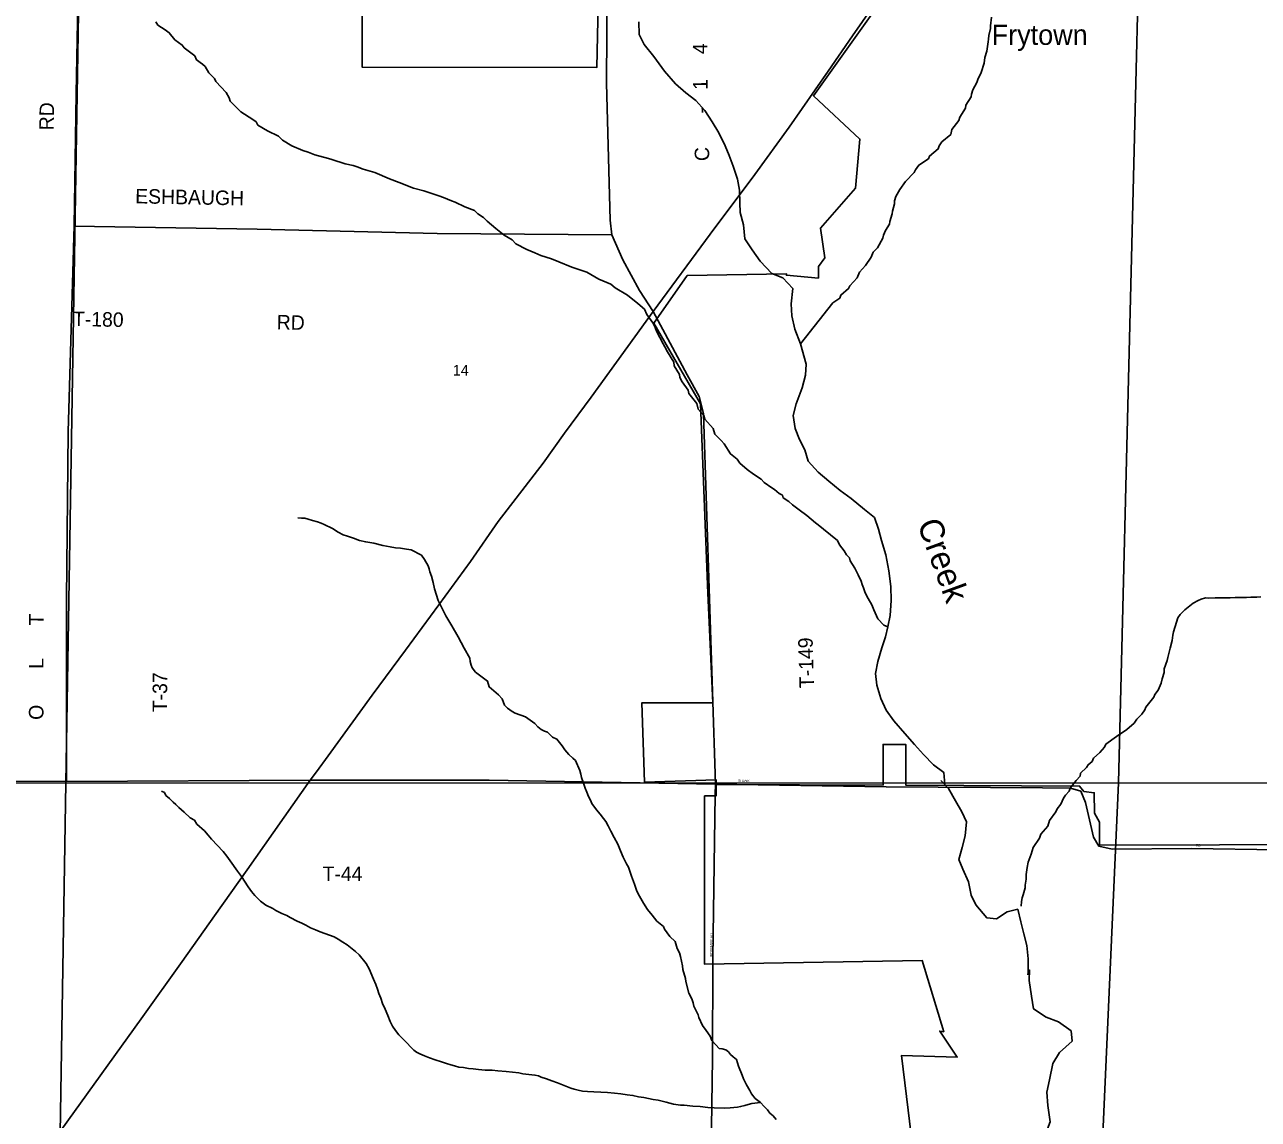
# Model space of a CAD drawing. Extents: x 1312308 to 1684953, y 460642 to 865172.
# Drawn here: x 1464469 to 1470845, y 623330 to 628989 of the extents above; entities that cross this region are included whole.
import ezdxf

# ---------------------------------------------------------------- set-up
doc = ezdxf.new("R2010")
doc.units = 0
for name, color, linetype in [('GM_X_City_Street', 7, 'Continuous'), ('GM_X_City_Street_Text', 7, 'Continuous'), ('GM_X_Corporation', 7, 'Continuous'), ('GM_X_County_Road', 7, 'Continuous'), ('GM_X_County_Road_Text', 7, 'Continuous'), ('GM_X_Minor_River', 7, 'Continuous'), ('GM_X_Minor_River_Text', 7, 'Continuous'), ('GM_X_Section', 7, 'Continuous'), ('GM_X_Section_Text', 7, 'Continuous'), ('GM_X_State_Route', 7, 'Continuous'), ('GM_X_Township_Road', 7, 'Continuous'), ('GM_X_Township_Road_Text', 7, 'Continuous'), ('GM_X_Unincorporated_Text', 7, 'Continuous')]:
    doc.layers.add(name, color=color, linetype=linetype)

msp = doc.modelspace()

# ---------------------------------------------------------------- linework, layer by layer
at = {"layer": 'GM_X_City_Street'}
for points in [[(1468038.3, 625009.5), (1468039.1, 625062.4), (1468023.7, 625542.1)], [(1468026.3, 624163), (1468038.3, 625009.5)], [(1468039.1, 625062.4), (1468920.9, 625048.3), (1469729.1, 625044.2), (1469873.4, 625042.2), (1469927.1, 625026.7), (1469951.5, 624967.8), (1469992.5, 624788.1), (1470019.9, 624742.8), (1470089, 624727.2), (1470498.2, 624730), (1470950.3, 624722.5), (1471309.2, 624721.6)]]:
    msp.add_lwpolyline(points, dxfattribs=at)
at = {"layer": 'GM_X_Corporation'}
for points in [[(1467456.4, 630241.5), (1467426.6, 628767.9), (1466212.4, 628769.8), (1466212.4, 629213.7)], [(1471264.1, 624750.7), (1470023.6, 624747.6), (1470024, 624865.5), (1469998.5, 624912.4), (1469996.5, 625018.4), (1469943.5, 625025.5), (1469920.5, 625053.1), (1469022.4, 625058.3), (1469022.4, 625268.4), (1468905.4, 625268.3), (1468905.4, 625058.3), (1468042.8, 625060.8), (1468042, 625085.8), (1467672.7, 625072.9), (1467658.4, 625482.7), (1468025.4, 625482.8), (1467999.5, 626049.3), (1467962.4, 627028.9), (1467721.4, 627446.5), (1467893.5, 627692.2), (1468405.9, 627701.2), (1468405.9, 627693.2), (1468571.2, 627678.8), (1468571.2, 627738.8), (1468604.3, 627782.7), (1468582.8, 627936.2), (1468763.2, 628143.7), (1468785.4, 628397.7), (1468545.3, 628621.6), (1468958.7, 629201.3)], [(1469152.5, 622416.7), (1469001.4, 623660.4), (1469288.4, 623652.1), (1469198, 623786), (1469219.3, 623782.7), (1469106.6, 624151.5), (1467983.1, 624131.8), (1467983.1, 625002), (1468042.6, 625002.4), (1468042.8, 625060.8), (1468905.4, 625058.3), (1468905.4, 625268.3), (1469022.4, 625268.4), (1469022.4, 625058.3), (1469920.5, 625053.1), (1469943.5, 625025.5), (1469996.5, 625018.4), (1469998.5, 624912.4), (1470024, 624865.5), (1470023.6, 624747.6), (1471264.1, 624750.7)]]:
    msp.add_lwpolyline(points, dxfattribs=at)
at = {"layer": 'GM_X_County_Road'}
for points in [[(1467717.9, 627505.5), (1467645.7, 627614.5), (1467560.2, 627773), (1467503.6, 627902.5), (1467495.6, 627978), (1467475.9, 628686), (1467479.7, 629209.1), (1467509.4, 630147.5), (1467518.7, 630244.5), (1467561.4, 630362.2), (1467592.2, 630460.3), (1467604.8, 630537.3), (1467608.5, 630663.9), (1467609.8, 630907.3), (1467613.5, 631151.9), (1467614.1, 631178.6)], [(1454210.5, 625100.4), (1455352.9, 625087.9), (1456190.5, 625056.2), (1456967.8, 625063.2), (1457105.9, 625064), (1457396.6, 625065.8), (1458239.8, 625063.3), (1459213.3, 625064), (1459508.2, 625062.6), (1459800.2, 625061.2), (1461104, 625081.4), (1462543.4, 625079.9), (1464684.9, 625077), (1465945, 625083.6)]]:
    msp.add_lwpolyline(points, dxfattribs=at)
at = {"layer": 'GM_X_Minor_River'}
for points in [[(1468479.3, 627338.4), (1468646.5, 627551.6), (1468681.4, 627574.9), (1468687.8, 627590.8), (1468726.9, 627624.1), (1468733.3, 627638), (1468770.6, 627679.3), (1468783.4, 627709.1), (1468814.5, 627744.6), (1468843.8, 627786.1), (1468854.5, 627812), (1468877.3, 627835.5), (1468904.7, 627885.1), (1468907.1, 627901.2), (1468917.8, 627925), (1468938.8, 627956.7), (1468941.1, 627970.7), (1468952.2, 628010.7), (1468954.6, 628024.7), (1468963.6, 628062.7), (1468964.1, 628078.7), (1468970.7, 628100.7), (1468991.7, 628136.4), (1469021, 628177.9), (1469066.5, 628225), (1469072.9, 628238.9), (1469089.6, 628262.7), (1469140.7, 628295.6), (1469145.1, 628309.6), (1469190.4, 628346.7), (1469194.8, 628362.7), (1469209.4, 628382.4), (1469254.7, 628421.5), (1469261.4, 628447.5), (1469296.8, 628492.9), (1469301.3, 628510.8), (1469330.6, 628556.4), (1469333.1, 628572.4), (1469360.4, 628616), (1469362.7, 628630), (1469369.3, 628651.9), (1469390.4, 628689.6), (1469394.9, 628705.6), (1469411.9, 628741.4), (1469427.2, 628789.2), (1469432, 628819.3), (1469440.9, 628851.2), (1469448.2, 628899.3), (1469450.6, 628913.3), (1469451.1, 628933.4), (1469460.1, 628969.4), (1469460.4, 628983.4), (1469465.6, 629027.5)], [(1465849.6, 628363.1), (1465802.1, 628392.4), (1465780.5, 628413), (1465724.8, 628440.5), (1465673.2, 628469.9), (1465665.6, 628486.1), (1465647.8, 628498.6), (1465586.4, 628538.3), (1465531.5, 628593.9), (1465525.9, 628610.1), (1465510.5, 628638.7), (1465457.6, 628694.2), (1465450, 628710.5), (1465420.5, 628739.3), (1465401.3, 628772), (1465387.5, 628784.4), (1465357.9, 628807.2), (1465348.4, 628827.5), (1465293.1, 628869.1), (1465283.4, 628883.4), (1465245.8, 628910.4), (1465216.6, 628947.3), (1465194.8, 628961.9), (1465157.2, 628986.9), (1465147.6, 629003.3)], [(1469224, 625060.2), (1469218.7, 625123.5), (1469165.5, 625163.2), (1469114.8, 625216.8), (1469067.9, 625268.3), (1469017.2, 625323.9), (1468960.7, 625389.8), (1468922, 625445), (1468893.5, 625506.1), (1468873.3, 625574.9), (1468866.9, 625635.3), (1468878.7, 625697.2), (1468898.6, 625766.9), (1468918.3, 625824.6), (1468929.8, 625876.5), (1468941.4, 625934.4), (1468947.5, 626012.5), (1468945.5, 626084.8), (1468935.6, 626165.4), (1468919.8, 626248.2), (1468897.7, 626323), (1468881.2, 626381.7), (1468860.7, 626440.5), (1468809.6, 626482.1), (1468740.9, 626540.2), (1468683.7, 626580), (1468624.7, 626629.8), (1468569.7, 626675.5), (1468519, 626733.1), (1468500.5, 626791.8), (1468473.8, 626844.8), (1468451.3, 626901.6), (1468441, 626968.1), (1468456.7, 627027.9), (1468487.1, 627111.4), (1468505, 627177.1), (1468508.5, 627233.2), (1468479.3, 627338.4), (1468449.2, 627415.5), (1468433, 627484.2), (1468430.7, 627546.5), (1468438.8, 627624.6), (1468388.1, 627680.2), (1468330.4, 627701.9), (1468269.8, 627765.8), (1468229.3, 627825.1), (1468190.6, 627882.4), (1468184.6, 627954.8), (1468166.2, 628017.6), (1468165.5, 628067.8), (1468163.3, 628134.1), (1468152.8, 628190.6), (1468130.5, 628257.4), (1468109.9, 628312.2), (1468089.2, 628362.9), (1468056.8, 628430.1), (1468022.2, 628487.2), (1467983.6, 628544.5), (1467936.8, 628596), (1467885.6, 628635.6), (1467832.6, 628683.2), (1467776.1, 628749), (1467719.9, 628824.9), (1467671.4, 628886.4), (1467644.6, 628937.4), (1467642.4, 629003.7)], [(1468929.8, 625876.5), (1468909.4, 625884.4), (1468878.1, 625917.4), (1468857.1, 625964.1), (1468847.8, 625990.5), (1468828.5, 626023.1), (1468813.1, 626051.7), (1468803.7, 626078), (1468798.1, 626094.2), (1468792.5, 626112.5), (1468777.3, 626145), (1468760.1, 626179.6), (1468734.8, 626216.4), (1468731.2, 626232.6), (1468715.5, 626249), (1468704, 626269.4), (1468680.6, 626300.2), (1468669.1, 626322.6), (1468598.2, 626380.6), (1468570.6, 626403.4), (1468556.8, 626413.8), (1468511.4, 626451), (1468471.9, 626480.1), (1468436.4, 626507.2), (1468418.7, 626523.7), (1468389, 626542.5), (1468385.3, 626556.6), (1468367.5, 626565.1), (1468343.8, 626585.8), (1468330, 626594.2), (1468290.4, 626621.3), (1468274.8, 626639.7), (1468235.2, 626664.8), (1468203.6, 626689.7), (1468164.2, 626722.8), (1468150.7, 626743.3), (1468117.1, 626770.2), (1468084.2, 626821.3), (1468068.6, 626839.8), (1468035.2, 626872.7), (1468027.9, 626901), (1467984.9, 626950.3), (1467979.3, 626968.6), (1467950, 627001.4), (1467942.7, 627029.8), (1467901.8, 627083), (1467898.2, 627099.2), (1467867.1, 627142.2), (1467855.6, 627164.6), (1467854, 627180.7), (1467825, 627225.6), (1467823.4, 627243.8), (1467790.6, 627296.8), (1467777.2, 627323.3), (1467769.5, 627339.6), (1467735, 627404.8), (1467727.4, 627423), (1467716, 627447.4), (1467684.9, 627490.4), (1467671.5, 627518.9), (1467638, 627547.8), (1467584.8, 627591.3), (1467521.4, 627629), (1467497.7, 627647.7), (1467436, 627673.3), (1467374.5, 627709), (1467296.7, 627735), (1467229, 627762.8), (1467191.1, 627777.8), (1467137.2, 627795.2), (1467105.4, 627810), (1467063.6, 627827.1), (1467008, 627856.6), (1466988.4, 627877.2), (1466946.7, 627900.3), (1466903.3, 627935.5), (1466860, 627972.7), (1466840.4, 627991.3), (1466810.7, 628010.1), (1466793, 628028.6), (1466743.2, 628047.9), (1466693.5, 628071.3), (1466675.5, 628077.7), (1466633.7, 628094.8), (1466609.8, 628103.4), (1466557.9, 628120.8), (1466532, 628129.4), (1466478, 628142.8), (1466404.2, 628172.7), (1466354.4, 628192), (1466278.8, 628224), (1466218.8, 628241.5), (1466187, 628254.4), (1466167, 628260.9), (1466125, 628270), (1466057.1, 628291.7), (1466039.1, 628296.2), (1465969.2, 628315.9), (1465933.3, 628328.9), (1465907.3, 628337.5), (1465849.6, 628363.1)], [(1467138.4, 625346), (1467120.6, 625358.5), (1467105, 625377), (1467057.5, 625410.3), (1467003.7, 625429.7), (1466987.8, 625438.1), (1466964.1, 625454.8), (1466948.4, 625471.3), (1466937.1, 625503.7), (1466917.5, 625524.3), (1466870.3, 625565.7), (1466861, 625596), (1466799.8, 625641.8), (1466782.3, 625664.3), (1466776.6, 625678.5), (1466771, 625696.8), (1466769.5, 625714.9), (1466740.6, 625765.8), (1466709.9, 625824.9), (1466677.2, 625882), (1466646.3, 625933), (1466623.3, 625977.8), (1466606.1, 626012.4), (1466587.5, 626073.2), (1466580.3, 626105.5), (1466571.1, 626137.9), (1466563.6, 626160.2), (1466560, 626176.4), (1466554.3, 626190.6), (1466535.1, 626223.3), (1466519.5, 626245.8), (1466465.9, 626273.2), (1466441.9, 626277.8), (1466411.8, 626282.6), (1466385.7, 626285.2), (1466357.6, 626289.9), (1466319.6, 626296.8), (1466273.6, 626308), (1466231.5, 626315.1), (1466199.5, 626321.9), (1466167.6, 626334.7), (1466137.7, 626345.5), (1466115.7, 626352), (1466089.9, 626364.7), (1466060.2, 626383.5), (1466016.4, 626404.7), (1466000.5, 626411.1), (1465982.6, 626419.6), (1465956.6, 626426.3), (1465934.6, 626432.8), (1465916.6, 626437.3), (1465900.5, 626437.7), (1465880.5, 626440.2)], [(1469618.6, 624431.4), (1469621.2, 624455.4), (1469623.8, 624475.5), (1469630.2, 624491.4), (1469639.2, 624527.4), (1469639.6, 624541.5), (1469644.4, 624571.5), (1469645, 624595.7), (1469650, 624631.8), (1469654.7, 624659.8), (1469669.9, 624701.7), (1469680.8, 624735.6), (1469714.3, 624783), (1469720.9, 624805), (1469756.1, 624846.4), (1469764.9, 624874.3), (1469798.3, 624919.8), (1469804.7, 624935.7), (1469823.5, 624959.4), (1469838.4, 624991.2), (1469848.8, 625005.1), (1469867.5, 625026.7), (1469871.9, 625042.7), (1469903.1, 625082.2), (1469923.8, 625103.8), (1469926.2, 625119.8), (1469957.2, 625149.3), (1469965.6, 625163.1), (1469986.2, 625180.7), (1469992.6, 625196.7), (1470025.6, 625226), (1470050.5, 625253.6), (1470056.9, 625269.5), (1470112.3, 625308.4), (1470165.5, 625345.3), (1470202.6, 625378.6), (1470217.2, 625398.4), (1470242, 625423.9), (1470258.8, 625447.7), (1470263.1, 625461.6), (1470304.7, 625512.9), (1470309.1, 625526.9), (1470327.8, 625548.5), (1470342.8, 625584.4), (1470347.4, 625606.4), (1470358.3, 625640.3), (1470358.8, 625658.4), (1470374, 625702.3), (1470376.5, 625718.3), (1470389.8, 625766.2), (1470398.9, 625806.2), (1470403.6, 625832.3), (1470406, 625850.3), (1470421.4, 625900.2), (1470428, 625922.2), (1470440.6, 625940), (1470465.3, 625963.5), (1470508.5, 625998.7), (1470533, 626012.2), (1470549.3, 626019.8), (1470571.6, 626025.3), (1470587.7, 626024.9), (1470621.9, 626026.1), (1470646, 626025.5), (1470682.3, 626026.6), (1470698.4, 626026.2), (1470724.6, 626027.6), (1470744.7, 626027.1), (1470783, 626028.2), (1470805.2, 626029.7), (1470837.3, 626028.9), (1470857.5, 626030.4)], [(1468352.3, 623329.4), (1468336.7, 623347.9), (1468320.9, 623362.3), (1468307.3, 623378.8), (1468291.6, 623397.3), (1468272, 623417.8), (1468244.4, 623438.6), (1468224.9, 623461.2), (1468217.3, 623479.5), (1468199.9, 623508.1), (1468184.6, 623538.7), (1468177.1, 623558.9), (1468158.1, 623605.7), (1468147, 623640.2), (1468131.2, 623652.6), (1468117.4, 623665), (1468105.7, 623679.4), (1468091.9, 623689.8), (1468073.9, 623694.2), (1468057.9, 623696.6), (1468040.2, 623715.2), (1468020.7, 623737.8), (1468011.2, 623760.1), (1467991.8, 623788.7), (1467972.4, 623815.4), (1467953.3, 623856), (1467949.6, 623870.2), (1467926.6, 623915), (1467923.1, 623933.2), (1467917.6, 623953.5), (1467902.2, 623982), (1467885.7, 624042.7), (1467884.1, 624058.9), (1467871.2, 624105.4), (1467869.6, 624123.6), (1467858.8, 624172.1), (1467853.2, 624190.4), (1467841.7, 624212.8), (1467830.6, 624249.2), (1467803.1, 624276), (1467775.9, 624312.9), (1467770.2, 624327.1), (1467736.7, 624354.1), (1467711.3, 624384.9), (1467688, 624415.6), (1467666.7, 624448.3), (1467639.7, 624495.2), (1467630.2, 624515.6), (1467626.5, 624529.7), (1467620.9, 624546), (1467605.8, 624586.5), (1467588.9, 624633.2), (1467579.3, 624651.5), (1467562.1, 624686.2), (1467548.9, 624718.7), (1467533.7, 624753.2), (1467516.4, 624787.8), (1467499.2, 624820.4), (1467483.8, 624846.9), (1467472.3, 624869.3), (1467460.6, 624885.7), (1467443.1, 624908.3), (1467423.5, 624930.8), (1467400.2, 624963.6), (1467392.6, 624979.9), (1467383, 624998.2), (1467373.5, 625020.6), (1467366, 625042.9), (1467356.6, 625067.2), (1467347.3, 625097.6), (1467343.7, 625113.8), (1467338.2, 625134), (1467315.4, 625184.9), (1467301.6, 625197.3), (1467281.9, 625215.8), (1467260.4, 625240.5), (1467246.9, 625260.9), (1467219.6, 625295.8), (1467197.7, 625306.4), (1467170.2, 625331.2), (1467156.3, 625337.5), (1467138.4, 625346)], [(1469653.8, 624076.4), (1469654.8, 624091.3), (1469654.7, 624159.6), (1469648.5, 624228), (1469632.1, 624288.7), (1469617.7, 624351.4), (1469601.4, 624416.1), (1469546.8, 624403.5), (1469491.5, 624366.9), (1469441.4, 624372.4), (1469384.9, 624438.2), (1469360.2, 624489.1), (1469346, 624557.8), (1469317.6, 624622.8), (1469296.9, 624673.6), (1469314.7, 624735.3), (1469330.4, 624795.1), (1469336.3, 624867.2), (1469311.7, 624920.2), (1469279, 624977.3), (1469242.6, 625040.5), (1469203.5, 625081.8)], [(1465589, 624584.9), (1465569.6, 624613.6), (1465530.7, 624666.8), (1465513.3, 624691.4), (1465495.7, 624713.9), (1465435, 624777.7), (1465417.4, 624798.3), (1465397.8, 624820.9), (1465358.5, 624856), (1465346.9, 624876.4), (1465325.1, 624889), (1465293.7, 624917.9), (1465266.1, 624942.7), (1465250.4, 624957.2), (1465236.6, 624969.6), (1465217, 624988.2), (1465199.3, 625004.7), (1465191.6, 625018.9), (1465175.7, 625027.4)], [(1468272, 623417.8), (1468227.6, 623412.9), (1468207.4, 623407.3), (1468191.1, 623401.7), (1468168.8, 623396.2), (1468152.6, 623392.6), (1468114.3, 623389.5), (1468084.1, 623388.2), (1468031.8, 623389.4), (1467999.7, 623392.2), (1467959.5, 623397.2), (1467921.3, 623398.2), (1467877.2, 623403.2), (1467859.1, 623403.7), (1467823, 623408.6), (1467785, 623419.5), (1467743, 623428.6), (1467716.9, 623433.3), (1467668.9, 623442.5), (1467640.8, 623447.2), (1467612.8, 623453.9), (1467582.7, 623456.6), (1467550.6, 623461.4), (1467516.5, 623466.3), (1467480.3, 623469.2), (1467446.1, 623470), (1467410, 623472.9), (1467377.8, 623473.6), (1467351.7, 623476.3), (1467329.7, 623480.8), (1467309.7, 623485.3), (1467291.7, 623491.8), (1467247.9, 623509), (1467222, 623519.6), (1467194, 623528.4), (1467166.1, 623539.1), (1467138.2, 623547.8), (1467124.3, 623554.2), (1467106.3, 623558.7), (1467044.1, 623566.2), (1467022.1, 623570.7), (1466957.8, 623578.3), (1466913.6, 623581.4), (1466885.5, 623584.1), (1466849.3, 623585), (1466815.2, 623587.8), (1466787.1, 623590.5), (1466763, 623593.1), (1466736.9, 623597.8), (1466712.8, 623600.3), (1466690.9, 623606.9), (1466670.9, 623611.4), (1466648.9, 623618), (1466623, 623626.6), (1466591, 623637.5), (1466561.1, 623648.3), (1466535.2, 623658.9), (1466511.3, 623669.6), (1466493.4, 623678), (1466479.6, 623688.4), (1466463.9, 623702.9), (1466444.4, 623725.5), (1466422.8, 623746.1), (1466403.2, 623766.7), (1466385.6, 623789.3), (1466370.1, 623811.8), (1466358.7, 623836.2), (1466345.4, 623866.7), (1466332.1, 623899.2), (1466318.8, 623929.7), (1466309.4, 623956.1), (1466300, 623980.4), (1466292.5, 624002.8), (1466283.1, 624027.1), (1466271.7, 624055.5), (1466249, 624108.4), (1466233.5, 624134.9), (1466198.5, 624180), (1466178.8, 624198.6), (1466135.4, 624231.8), (1466113.6, 624246.4), (1466089.9, 624261.1), (1466068, 624273.7), (1466020.2, 624290.9), (1465996.3, 624299.6), (1465972.4, 624310.2), (1465946.5, 624320.9), (1465922.7, 624333.5), (1465900.8, 624344.1), (1465876.9, 624354.7), (1465841.2, 624373.7), (1465823.3, 624384.2), (1465797.4, 624394.9), (1465767.6, 624409.7), (1465751.8, 624420.1), (1465716, 624437.1), (1465688.4, 624457.8), (1465658.9, 624486.7), (1465641.3, 624507.3), (1465623.9, 624531.8), (1465589, 624584.9)], [(1469654.8, 624091.3), (1469662.7, 624102.2), (1469659.6, 624048.1), (1469672.1, 623967.5), (1469682.8, 623901.1), (1469748.2, 623857.7), (1469812, 623834.3), (1469877.4, 623786.9), (1469882.4, 623734.6), (1469816.8, 623675.6), (1469783.5, 623618), (1469765.7, 623534.1), (1469752.3, 623470.1), (1469757, 623401.7), (1469769.3, 623317.2), (1469726.2, 623203.5)]]:
    msp.add_lwpolyline(points, dxfattribs=at)
at = {"layer": 'GM_X_Section'}
for points in [[(1459585.8, 630367.6), (1464768, 630305.4), (1464682.6, 625067.6), (1459521.5, 625085.3)], [(1464768, 630305.4), (1470249.6, 630219.1), (1470122, 625070.3), (1464682.6, 625067.6)], [(1475570.1, 630176.2), (1475511.2, 625059.9), (1470122, 625070.3), (1470249.6, 630219.1)], [(1459521.5, 625085.3), (1464682.6, 625067.6), (1464595.6, 619745.9), (1459424.8, 619777.8)], [(1464682.6, 625067.6), (1470122, 625070.3), (1469882, 619697.7), (1464595.6, 619745.9)], [(1470122, 625070.3), (1475511.2, 625059.9), (1475465.2, 620489.4), (1473558.4, 620339.7), (1471829.4, 619676.5), (1469882, 619697.7)]]:
    msp.add_lwpolyline(points, close=True, dxfattribs=at)
at = {"layer": 'GM_X_State_Route'}
for points in [[(1467717.9, 627505.5), (1468012.5, 627905.4), (1468242.3, 628214.9), (1468419.4, 628459.6), (1468621.7, 628748.3), (1468747.5, 628931.3), (1468954.2, 629229.1), (1468977, 629262.5)], [(1465976.9, 625126.7), (1466037.3, 625208.7), (1466265.7, 625523.4), (1466436.8, 625754.7), (1466608.6, 625989), (1466772.3, 626213), (1466916.7, 626421.3), (1467148, 626721.8), (1467258.1, 626876.6), (1467397.2, 627063.3), (1467717.9, 627505.5)], [(1464655.1, 623272.2), (1465071, 623849.5), (1465283, 624146.3), (1465449.6, 624381.4), (1465618.5, 624619.5), (1465945, 625083.6), (1465976.9, 625126.7)]]:
    msp.add_lwpolyline(points, dxfattribs=at)
at = {"layer": 'GM_X_Township_Road'}
for points in [[(1464723.5, 627895.7), (1464725.1, 627947.9), (1464734.6, 628633.3), (1464748.6, 629376), (1464759.9, 630250.4), (1464770.9, 630286.2), (1464796.6, 630302.7), (1464926.8, 630298.1), (1464958.9, 630308.3), (1464969.9, 630338.5), (1464976.4, 630379.8), (1464974.1, 630920.1), (1464979.2, 631455.2), (1464979.2, 631910.1), (1464983, 632134)], [(1464725.1, 627947.9), (1465670.4, 627930.9), (1466600.7, 627909.8), (1467503.6, 627902.5)], [(1464684.9, 625077), (1464684.8, 626019.5), (1464693.5, 626884.2), (1464721.3, 627827.6), (1464723.5, 627895.7)], [(1468023.7, 625542.1), (1467977.6, 626978.6), (1467954.2, 627066.4), (1467893.4, 627177.8), (1467717.9, 627505.5)], [(1465945, 625083.6), (1466868.9, 625082.8), (1468039.1, 625062.4)], [(1468019, 622417.4), (1468007, 622679.9), (1468012.7, 622930.6), (1468023.1, 623644.9), (1468026.1, 624148.5), (1468026.3, 624163)]]:
    msp.add_lwpolyline(points, dxfattribs=at)

# ---------------------------------------------------------------- texts
at = {"layer": 'GM_X_City_Street_Text'}
for s, rotation, p in [('SHANK', 358.80717, (1468155.9, 625074.6)), ('RD', 0.00001, (1470522.9, 624740.2)), ('INFIRMARY RD', 89.43086, (1468023.3, 624167.7))]:
    msp.add_text(s, height=12.5, rotation=rotation, dxfattribs=at).set_placement(p)
at = {"layer": 'GM_X_County_Road_Text'}
for s, rotation, p in [('4', 89.76582, (1467997, 628836.3)), ('1', 90.42673, (1467998.4, 628652.5)), ('-', 91.03823, (1468000.6, 628530.1)), ('C', 91.6902, (1468007.9, 628284.7))]:
    msp.add_text(s, height=75, rotation=rotation, dxfattribs=at).set_placement(p)
at = {"layer": 'GM_X_Minor_River_Text'}
msp.add_text('Creek', height=125, rotation=290.15171, dxfattribs=at).set_placement((1469080.3, 626409.3))
at = {"layer": 'GM_X_Section_Text'}
msp.add_text('14', height=55.25, rotation=0.00001, dxfattribs=at).set_placement((1466681.7, 627174.8))
at = {"layer": 'GM_X_Township_Road_Text'}
for s, rotation, p in [('RD', 89.01275, (1464619, 628442.1)), ('ESHBAUGH', 358.86856, (1465039.5, 628065.3)), ('T-180', 358.87626, (1464717.9, 627431)), ('RD', 358.51749, (1465770.8, 627414.1)), ('T', 89.0228, (1464566.2, 625882.3)), ('T-149', 91.68485, (1468548.6, 625560.1)), ('L', 89.95713, (1464566.1, 625659.2)), ('T-37', 89.66378, (1465204.8, 625434.4)), ('O', 90, (1464566.1, 625395.2)), ('T-44', 0.00001, (1466008.5, 624562.1))]:
    msp.add_text(s, height=75, rotation=rotation, dxfattribs=at).set_placement(p)
at = {"layer": 'GM_X_Unincorporated_Text'}
msp.add_text('Frytown', height=104.25, rotation=0.00001, dxfattribs=at).set_placement((1469466.9, 628884.2))

doc.saveas('drawing.dxf')
